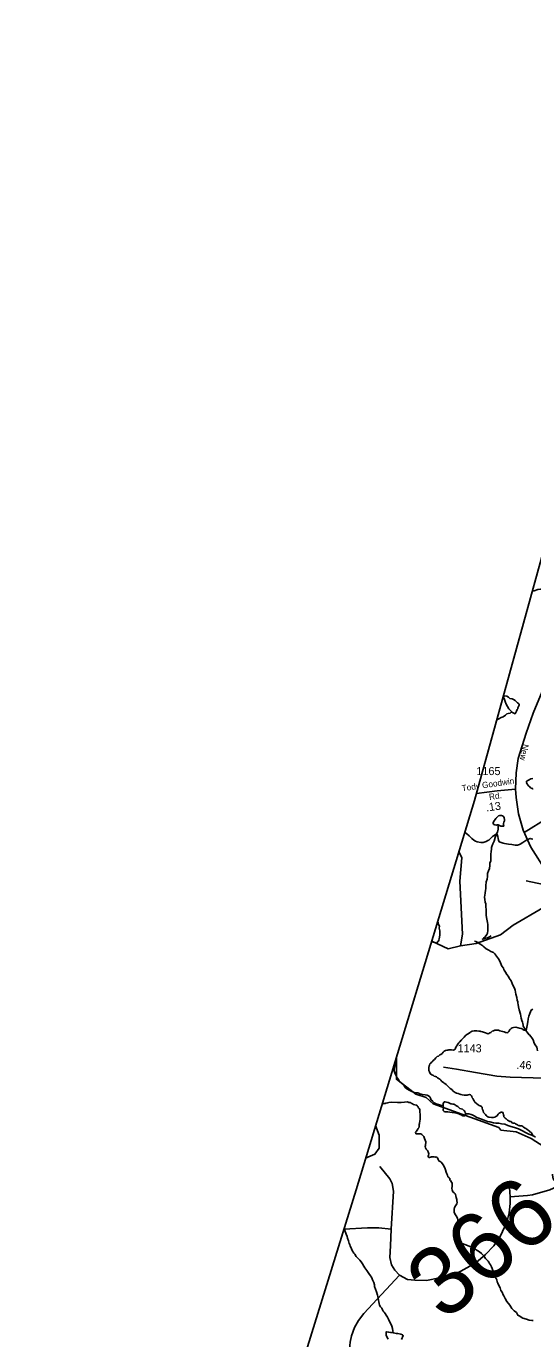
# Model space of a CAD drawing. Extents: x 2001466 to 2224147, y 644118 to 847247.
# Drawn here: x 2006818 to 2014651, y 709402 to 729712 of the extents above; entities that cross this region are included whole.
import ezdxf

# ---------------------------------------------------------------- set-up
doc = ezdxf.new("R2010")
doc.units = 0
for name, color, linetype in [('Exist Boundary Political CountyLine', 7, 'Continuous'), ('Exist Hydrographic Creek Single Shore', 7, 'Continuous'), ('Exist Hydrographic Misc Water Feature', 7, 'Continuous'), ('Exist Road Non-System Type 51', 7, 'Continuous'), ('Exist Road Secondary Mileage Hundredths English Label', 7, 'Continuous'), ('Exist Road Secondary Structure Standard Bridge CELL', 7, 'Continuous'), ('Exist Road Secondary Structure Standard Bridge Number Label', 7, 'Continuous'), ('Exist Road Secondary Type 20 Attributed', 7, 'Continuous'), ('Exist Road Secondary Type 41 Attributed', 7, 'Continuous'), ('Exist Road Secondary Type 51 Attributed', 7, 'Continuous'), ('Exist Road Secondary Type 51 Label', 7, 'Continuous'), ('Exist Road Secondary Type 51 Number Label', 7, 'Continuous')]:
    doc.layers.add(name, color=color, linetype=linetype)

msp = doc.modelspace()

# ---------------------------------------------------------------- linework, layer by layer
at = {"layer": 'Exist Boundary Political CountyLine'}
msp.add_lwpolyline([(2006818, 695750), (2007499, 697711), (2010413, 706845), (2011918, 711706), (2013749, 717730), (2014942, 722041), (2015285, 723239), (2015750, 724659), (2016153, 726118), (2016502, 727374), (2016861, 728619), (2017412, 730567), (2017757, 731851), (2018084, 732957), (2018350, 733870), (2018833, 735585), (2018918, 735898), (2019734, 740138), (2020503, 744108), (2021806, 746808), (2022822, 749625), (2023527, 751603)], dxfattribs=at)
at = {"layer": 'Exist Hydrographic Creek Single Shore'}
for points in [[(2013533, 715484), (2013775, 715519), (2014150, 715652), (2014349, 715802), (2014807, 716069), (2014941, 716176), (2014982, 716203), (2015055, 716229), (2015100, 716249), (2015170, 716309), (2015479, 716531)], [(2013088, 715555), (2013341, 715436), (2013533, 715484)]]:
    msp.add_lwpolyline(points, dxfattribs=at)
at = {"layer": 'Exist Hydrographic Misc Water Feature'}
for points in [[(2014986, 721093), (2014988, 721081), (2014988, 721063), (2014986, 721041), (2014980, 721031), (2014966, 721015), (2014938, 721007), (2014898, 721013), (2014866, 721017), (2014812, 721011), (2014772, 721001), (2014730, 720995), (2014672, 720977), (2014646, 720974)], [(2014331, 719099), (2014281, 719151), (2014239, 719219), (2014225, 719261), (2014215, 719293), (2014203, 719319), (2014201, 719331), (2014211, 719353), (2014249, 719343), (2014275, 719329), (2014283, 719323), (2014299, 719311), (2014331, 719305), (2014355, 719295), (2014379, 719279), (2014395, 719265), (2014417, 719243), (2014431, 719233), (2014437, 719227), (2014439, 719217), (2014439, 719207), (2014431, 719187), (2014423, 719165), (2014419, 719151), (2014411, 719137), (2014399, 719115), (2014389, 719091), (2014385, 719081), (2014379, 719073), (2014337, 719091), (2014331, 719099)], [(2014331, 719099), (2014313, 719091), (2014303, 719083), (2014271, 719075), (2014253, 719071), (2014229, 719053), (2014193, 719027), (2014165, 719015), (2014129, 718993), (2014094, 718977)], [(2014656, 717915), (2014646, 717911), (2014641, 717915), (2014619, 717927), (2014608, 717941), (2014593, 717953), (2014585, 717959), (2014574, 717973), (2014566, 717983), (2014553, 718007), (2014551, 718017), (2014566, 718035), (2014585, 718047), (2014621, 718065), (2014651, 718069)], [(2014114, 717353), (2014100, 717353), (2014090, 717351), (2014064, 717353), (2014050, 717361), (2014040, 717373), (2014040, 717383), (2014044, 717399), (2014056, 717415), (2014068, 717437), (2014080, 717451), (2014084, 717457), (2014090, 717465), (2014094, 717467), (2014106, 717479), (2014124, 717491), (2014142, 717499), (2014168, 717497), (2014184, 717495), (2014194, 717489), (2014204, 717479), (2014210, 717461), (2014214, 717439), (2014214, 717415), (2014204, 717395), (2014200, 717377), (2014200, 717359), (2014202, 717335), (2014188, 717333), (2014156, 717333), (2014128, 717349), (2014114, 717353)], [(2014088, 717211), (2014078, 717203), (2014070, 717201), (2014046, 717183), (2014028, 717173), (2014008, 717151), (2013972, 717119), (2013958, 717111), (2013930, 717095), (2013914, 717091), (2013882, 717083), (2013864, 717083), (2013846, 717083), (2013792, 717091), (2013766, 717101), (2013742, 717117), (2013710, 717145), (2013684, 717167), (2013670, 717183), (2013634, 717215), (2013608, 717237), (2013600, 717241)], [(2014088, 717211), (2014086, 717199), (2014068, 717159), (2014052, 717099), (2014044, 717081), (2014032, 717059), (2014016, 717021), (2014014, 717003), (2014014, 716977), (2014008, 716939), (2014004, 716899), (2014004, 716843), (2014002, 716799), (2013990, 716759), (2013986, 716727), (2013980, 716677), (2013968, 716641), (2013950, 716601), (2013950, 716557), (2013944, 716515), (2013931, 716471), (2013926, 716409), (2013928, 716381), (2013924, 716365), (2013920, 716345), (2013915, 716295), (2013907, 716237), (2013909, 716201), (2013917, 716159), (2013925, 716133), (2013927, 716093), (2013929, 716039), (2013931, 715951), (2013941, 715895), (2013949, 715845), (2013955, 715813), (2013957, 715785), (2013955, 715747), (2013955, 715721), (2013951, 715679), (2013939, 715659), (2013913, 715623), (2013887, 715599), (2013867, 715581)], [(2014114, 717353), (2014114, 717345), (2014118, 717287), (2014104, 717243), (2014088, 717211)], [(2014652, 717131), (2014626, 717139), (2014610, 717145), (2014562, 717123), (2014528, 717101), (2014514, 717089), (2014496, 717079), (2014458, 717057), (2014446, 717051), (2014432, 717045), (2014414, 717039), (2014380, 717041), (2014352, 717045), (2014326, 717051), (2014276, 717055), (2014216, 717065), (2014192, 717073), (2014162, 717083), (2014146, 717087), (2014134, 717093), (2014124, 717115), (2014114, 717145), (2014110, 717173), (2014104, 717191), (2014100, 717205), (2014088, 717211)], [(2013533, 715484), (2013566, 715661), (2013524, 716485), (2013557, 716845), (2013509, 716941)], [(2013181, 715862), (2013195, 715812), (2013207, 715788), (2013205, 715754), (2013215, 715714), (2013215, 715682), (2013213, 715654), (2013209, 715616), (2013203, 715591), (2013199, 715572), (2013193, 715556), (2013185, 715548), (2013175, 715532), (2013169, 715528), (2013159, 715522)], [(2013159, 715522), (2013149, 715526), (2013117, 715538), (2013097, 715548), (2013087, 715553)], [(2014544, 714173), (2014524, 714207), (2014504, 714241), (2014502, 714255), (2014500, 714279), (2014492, 714299), (2014484, 714327), (2014473, 714365), (2014460, 714423), (2014439, 714491), (2014431, 714537), (2014427, 714573), (2014423, 714593), (2014419, 714613), (2014411, 714639), (2014403, 714681), (2014391, 714733), (2014377, 714795), (2014367, 714829), (2014349, 714861), (2014335, 714897), (2014319, 714939), (2014289, 714981), (2014277, 715009), (2014251, 715037), (2014229, 715075), (2014211, 715103), (2014205, 715117), (2014199, 715135), (2014175, 715165), (2014155, 715217), (2014141, 715247), (2014121, 715283), (2014093, 715321), (2014087, 715329), (2014081, 715335), (2014065, 715357), (2014045, 715377), (2014003, 715395), (2013971, 715417), (2013933, 715435), (2013895, 715465), (2013877, 715481), (2013849, 715501), (2013825, 715517), (2013801, 715533), (2013769, 715547), (2013749, 715555)], [(2014007, 715637), (2013981, 715619), (2013953, 715607), (2013927, 715601), (2013895, 715589), (2013867, 715581)], [(2014544, 714173), (2014554, 714191), (2014562, 714223), (2014566, 714251), (2014569, 714273), (2014576, 714309), (2014580, 714341), (2014580, 714351), (2014590, 714391), (2014604, 714435), (2014615, 714461), (2014627, 714487), (2014655, 714503)], [(2014544, 714173), (2014520, 714177), (2014496, 714189), (2014488, 714195), (2014472, 714201), (2014446, 714207), (2014424, 714213), (2014390, 714221), (2014356, 714217), (2014334, 714213), (2014316, 714201), (2014300, 714187), (2014294, 714183), (2014290, 714177), (2014280, 714157), (2014268, 714143), (2014252, 714137), (2014236, 714139), (2014230, 714143), (2014208, 714149), (2014184, 714157), (2014162, 714163), (2014142, 714169), (2014122, 714175), (2014094, 714177), (2014078, 714177), (2014066, 714175), (2014042, 714169), (2014026, 714163), (2014016, 714155), (2014004, 714143), (2013990, 714133), (2013972, 714123), (2013956, 714119), (2013944, 714123), (2013918, 714135), (2013904, 714139), (2013890, 714147), (2013874, 714149), (2013850, 714157), (2013836, 714161), (2013816, 714163), (2013788, 714167), (2013766, 714169), (2013744, 714165), (2013714, 714159), (2013694, 714151), (2013682, 714143), (2013674, 714137), (2013666, 714131), (2013644, 714115), (2013616, 714097), (2013590, 714071), (2013578, 714057), (2013564, 714041), (2013550, 714027), (2013544, 714019), (2013536, 714011), (2013532, 714009), (2013524, 714003), (2013516, 713991), (2013506, 713979), (2013486, 713953), (2013476, 713935), (2013464, 713913), (2013458, 713899), (2013452, 713883), (2013440, 713875), (2013436, 713873), (2013418, 713869), (2013394, 713873), (2013368, 713875), (2013352, 713873), (2013340, 713869), (2013320, 713867), (2013300, 713863), (2013282, 713851), (2013266, 713837), (2013250, 713815), (2013232, 713801), (2013216, 713793), (2013192, 713777), (2013174, 713767), (2013154, 713751), (2013132, 713725), (2013112, 713709), (2013094, 713689), (2013084, 713681), (2013074, 713667), (2013062, 713655), (2013056, 713637), (2013048, 713625), (2013044, 713597), (2013042, 713575), (2013044, 713555), (2013050, 713543), (2013056, 713531), (2013062, 713519), (2013072, 713499), (2013090, 713487)], [(2014724, 713858), (2014722, 713888), (2014712, 713916), (2014690, 713948), (2014672, 713976), (2014658, 714025), (2014638, 714057), (2014620, 714078), (2014600, 714104), (2014596, 714107), (2014558, 714149), (2014544, 714173)], [(2014160, 712627), (2014126, 712670), (2013109, 713035), (2013001, 713136), (2012843, 713185), (2012543, 713418), (2012542, 713759)], [(2013079, 713094), (2013074, 713111), (2013068, 713125), (2013062, 713143), (2013040, 713159), (2013018, 713169), (2012986, 713177), (2012946, 713181), (2012928, 713187), (2012916, 713189), (2012896, 713199), (2012890, 713201), (2012874, 713207), (2012850, 713207), (2012816, 713214), (2012770, 713234), (2012748, 713244), (2012704, 713268), (2012680, 713292), (2012664, 713316), (2012628, 713350), (2012590, 713384), (2012576, 713412), (2012556, 713440), (2012534, 713478), (2012520, 713516), (2012508, 713550), (2012506, 713574), (2012514, 713596), (2012518, 713624), (2012522, 713654), (2012516, 713671), (2012518, 713678)], [(2013090, 713487), (2013114, 713473), (2013128, 713467), (2013148, 713461), (2013162, 713457), (2013180, 713441), (2013214, 713417), (2013230, 713405), (2013246, 713385), (2013272, 713365), (2013282, 713357), (2013294, 713349), (2013310, 713337), (2013334, 713313), (2013360, 713291), (2013374, 713273), (2013398, 713257), (2013422, 713235), (2013436, 713223), (2013450, 713213), (2013474, 713203), (2013496, 713197), (2013524, 713189), (2013540, 713183), (2013562, 713177), (2013592, 713173), (2013624, 713171), (2013638, 713173), (2013652, 713175), (2013674, 713179), (2013688, 713175), (2013694, 713171), (2013706, 713159), (2013708, 713151), (2013716, 713131), (2013722, 713117), (2013734, 713099), (2013746, 713083), (2013756, 713063), (2013774, 713049), (2013782, 713043), (2013788, 713037), (2013806, 713023), (2013822, 713013), (2013836, 713007), (2013850, 713001), (2013860, 712995), (2013868, 712985), (2013870, 712971), (2013876, 712947), (2013884, 712927), (2013892, 712905), (2013904, 712889), (2013920, 712873), (2013933, 712855), (2013941, 712847), (2013958, 712835), (2013971, 712831), (2014015, 712825), (2014042, 712825), (2014063, 712831), (2014080, 712841), (2014100, 712853), (2014108, 712861), (2014116, 712875), (2014126, 712887), (2014132, 712893), (2014152, 712905), (2014164, 712907), (2014170, 712907), (2014182, 712907), (2014192, 712893), (2014200, 712869), (2014204, 712851), (2014206, 712837), (2014224, 712813), (2014242, 712803), (2014252, 712795), (2014262, 712785), (2014270, 712779), (2014299, 712765), (2014316, 712761), (2014331, 712745), (2014347, 712738), (2014356, 712738), (2014369, 712736), (2014374, 712736), (2014387, 712726), (2014403, 712718), (2014414, 712712), (2014427, 712704), (2014443, 712700), (2014454, 712698), (2014467, 712698), (2014483, 712698), (2014499, 712688), (2014510, 712678), (2014534, 712662), (2014546, 712654), (2014558, 712644)], [(2012323, 713036), (2012330, 713038), (2012346, 713042), (2012368, 713042), (2012381, 713048), (2012407, 713052), (2012423, 713056), (2012468, 713064), (2012559, 713060), (2012617, 713060), (2012670, 713062), (2012716, 713066), (2012737, 713060), (2012763, 713056), (2012773, 713048), (2012792, 713035), (2012808, 713025), (2012830, 713021), (2012848, 713017), (2012856, 713015), (2012864, 713007), (2012869, 713001), (2012872, 712997), (2012885, 712977), (2012893, 712965), (2012903, 712947), (2012906, 712915), (2012909, 712871), (2012911, 712849), (2012911, 712821), (2012909, 712795), (2012903, 712773), (2012901, 712733), (2012897, 712717), (2012893, 712685), (2012887, 712665), (2012881, 712657), (2012873, 712647), (2012863, 712629), (2012853, 712615), (2012841, 712605), (2012837, 712595), (2012841, 712581), (2012845, 712575), (2012853, 712573), (2012865, 712573), (2012881, 712573), (2012899, 712573), (2012911, 712575), (2012921, 712573), (2012937, 712561), (2012953, 712549), (2012967, 712529), (2012979, 712501), (2012985, 712475), (2012997, 712447), (2012999, 712435), (2012995, 712407), (2012995, 712393), (2012989, 712375), (2012991, 712357), (2013001, 712337), (2013021, 712317), (2013031, 712303), (2013035, 712293), (2013041, 712279), (2013043, 712261), (2013037, 712243), (2013033, 712229), (2013035, 712215), (2013043, 712209), (2013049, 712205), (2013059, 712207), (2013067, 712209), (2013077, 712211), (2013087, 712215), (2013123, 712219), (2013145, 712213), (2013159, 712215), (2013173, 712205), (2013183, 712193), (2013187, 712177), (2013195, 712163), (2013201, 712153), (2013219, 712145), (2013237, 712133), (2013257, 712107), (2013267, 712095), (2013273, 712087), (2013277, 712073), (2013291, 712049), (2013303, 712015), (2013313, 711981), (2013321, 711955), (2013331, 711931), (2013339, 711909), (2013351, 711895), (2013359, 711887), (2013369, 711885)], [(2013268, 713015), (2013258, 713013), (2013226, 713017), (2013192, 713027), (2013172, 713033), (2013146, 713041), (2013126, 713051), (2013110, 713069), (2013102, 713079), (2013090, 713091), (2013079, 713094)], [(2013268, 713015), (2013268, 713025), (2013266, 713035), (2013268, 713043), (2013274, 713055), (2013278, 713061), (2013286, 713067), (2013298, 713067), (2013316, 713063), (2013342, 713055), (2013382, 713039), (2013394, 713035), (2013414, 713033), (2013430, 713031), (2013440, 713029), (2013450, 713021), (2013464, 713013), (2013490, 712995), (2013504, 712983), (2013518, 712971), (2013526, 712967), (2013544, 712961), (2013566, 712953), (2013584, 712935), (2013594, 712927), (2013599, 712919), (2013607, 712899), (2013609, 712891)], [(2013609, 712891), (2013613, 712890), (2013610, 712867), (2013604, 712857), (2013594, 712851), (2013572, 712851), (2013560, 712855), (2013544, 712865), (2013527, 712871), (2013517, 712877), (2013495, 712887), (2013472, 712893), (2013447, 712899), (2013405, 712903), (2013371, 712907), (2013336, 712913), (2013296, 712915), (2013283, 712919), (2013275, 712925), (2013268, 712933), (2013267, 712937), (2013268, 712955), (2013270, 712975), (2013270, 712987), (2013268, 712997), (2013268, 713015)], [(2012221, 712701), (2012277, 712553), (2012277, 712353), (2012210, 712260), (2012067, 712194)], [(2014647, 712548), (2014639, 712550), (2014590, 712566), (2014538, 712592), (2014491, 712620), (2014430, 712648), (2014369, 712671), (2014313, 712687), (2014268, 712701), (2014218, 712723), (2014170, 712725), (2014128, 712737), (2014079, 712737), (2014045, 712741), (2013989, 712757), (2013949, 712763), (2013899, 712783), (2013859, 712801), (2013801, 712821), (2013787, 712825), (2013745, 712849), (2013713, 712867), (2013698, 712873), (2013665, 712883), (2013634, 712883), (2013618, 712889), (2013613, 712890), (2013609, 712891)], [(2014626, 712502), (2014393, 712602), (2014160, 712627)], [(2014558, 712644), (2014566, 712638), (2014578, 712630), (2014594, 712618), (2014608, 712606), (2014623, 712596), (2014632, 712586), (2014639, 712578), (2014640, 712572), (2014645, 712568), (2014648, 712558), (2014647, 712548)], [(2016319, 710279), (2015952, 710405), (2015802, 710562), (2015485, 710720), (2015352, 710831), (2015244, 711013), (2015210, 711204), (2015169, 711271), (2015127, 711672), (2014968, 711878), (2014901, 712270), (2014826, 712370), (2014626, 712502)], [(2014696, 712524), (2014688, 712528), (2014647, 712548)], [(2013405, 711789), (2013403, 711807), (2013397, 711823), (2013379, 711851), (2013369, 711857), (2013369, 711867), (2013369, 711885)], [(2014656, 709684), (2014638, 709682), (2014596, 709690), (2014556, 709706), (2014496, 709722), (2014440, 709754), (2014422, 709766), (2014398, 709806), (2014362, 709836), (2014328, 709872), (2014296, 709920), (2014252, 709980), (2014226, 710022), (2014214, 710046), (2014202, 710064), (2014194, 710082), (2014176, 710120), (2014158, 710148), (2014146, 710192), (2014128, 710226), (2014110, 710260), (2014100, 710284), (2014094, 710312), (2014086, 710334), (2014072, 710354), (2014064, 710374), (2014056, 710408), (2014038, 710446), (2014024, 710488), (2014014, 710516), (2013996, 710546), (2013984, 710567), (2013974, 710585), (2013962, 710601), (2013946, 710619), (2013922, 710645), (2013894, 710683), (2013858, 710723), (2013828, 710749), (2013778, 710777), (2013768, 710787), (2013746, 710801), (2013708, 710821), (2013676, 710831), (2013614, 710857), (2013562, 710875), (2013539, 710885), (2013515, 710899), (2013488, 710919), (2013480, 710933), (2013470, 710941), (2013470, 710959), (2013470, 710971), (2013470, 710985), (2013466, 710995), (2013462, 711009), (2013468, 711039), (2013477, 711073), (2013476, 711113), (2013476, 711145), (2013473, 711167), (2013479, 711189), (2013492, 711213), (2013492, 711237), (2013487, 711269), (2013465, 711305), (2013455, 711319), (2013437, 711355), (2013437, 711377), (2013435, 711405), (2013439, 711435), (2013455, 711459), (2013465, 711473), (2013477, 711489), (2013481, 711509), (2013479, 711535), (2013475, 711547), (2013475, 711555), (2013471, 711573), (2013469, 711585), (2013461, 711613), (2013457, 711635), (2013449, 711645), (2013437, 711659), (2013415, 711677), (2013405, 711705), (2013401, 711725), (2013405, 711761), (2013405, 711789)], [(2012492, 709493), (2012487, 709525), (2012482, 709559), (2012472, 709595), (2012454, 709635), (2012437, 709669), (2012420, 709707), (2012406, 709737), (2012386, 709769), (2012368, 709791), (2012352, 709813), (2012338, 709831), (2012328, 709849), (2012316, 709873), (2012294, 709895), (2012282, 709921), (2012276, 709947), (2012270, 709973), (2012268, 709991), (2012260, 710029), (2012256, 710055), (2012252, 710076), (2012236, 710126), (2012218, 710171), (2012206, 710208), (2012202, 710238), (2012192, 710270), (2012174, 710312), (2012160, 710342), (2012154, 710362), (2012146, 710372), (2012128, 710398), (2012106, 710426), (2012084, 710460), (2012054, 710498), (2012040, 710526), (2012018, 710562), (2011998, 710590), (2011976, 710616), (2011954, 710638), (2011922, 710672), (2011898, 710708), (2011884, 710726), (2011860, 710766), (2011836, 710820), (2011828, 710834), (2011820, 710858), (2011812, 710876), (2011802, 710916), (2011788, 710958), (2011780, 710986), (2011764, 711022), (2011746, 711078), (2011735, 711115)], [(2012492, 709493), (2012466, 709499), (2012453, 709497), (2012425, 709501), (2012385, 709511), (2012383, 709497), (2012383, 709479), (2012386, 709457), (2012394, 709433), (2012413, 709397)], [(2012622, 709391), (2012649, 709451), (2012638, 709463), (2012609, 709473), (2012564, 709481), (2012540, 709485), (2012497, 709493), (2012492, 709493)]]:
    msp.add_lwpolyline(points, dxfattribs=at)
at = {"layer": 'Exist Road Non-System Type 51'}
for points in [[(2014519, 717236), (2014885, 717463), (2015336, 716757)], [(2014303, 711597), (2014568, 711616), (2014645, 711629), (2014914, 711706), (2015179, 711827), (2015419, 711978), (2015608, 712125), (2016167, 712627), (2016202, 712661), (2016254, 712704), (2016299, 712750)], [(2012462, 711098), (2012499, 711684), (2012476, 711804), (2012439, 711878), (2012288, 712069)], [(2014303, 711597), (2014284, 711815)], [(2012590, 710385), (2012714, 710319), (2012825, 710306), (2013009, 710305), (2013408, 710388), (2013539, 710446), (2013773, 710574), (2013923, 710705), (2014047, 710842), (2014153, 710996), (2014252, 711207), (2014284, 711348), (2014303, 711495), (2014303, 711597)], [(2012462, 711098), (2012272, 711118), (2012094, 711118), (2011729, 711095)], [(2012590, 710385), (2012516, 710462), (2012469, 710546), (2012442, 710660), (2012449, 710840), (2012462, 711098)], [(2011807, 709140), (2011825, 709349), (2011850, 709448), (2011894, 709578), (2011954, 709682), (2012041, 709793), (2012590, 710385)]]:
    msp.add_lwpolyline(points, dxfattribs=at)
at = {"layer": 'Exist Road Secondary Structure Standard Bridge CELL'}
msp.add_line((2014548, 716488), (2014818, 716430), dxfattribs=at)
at = {"layer": 'Exist Road Secondary Type 20 Attributed'}
msp.add_lwpolyline([(2015674, 713399), (2015401, 713412), (2014833, 713435), (2014303, 713451), (2014096, 713463), (2013767, 713521), (2013470, 713575), (2013269, 713604)], dxfattribs=at)
at = {"layer": 'Exist Road Secondary Type 41 Attributed'}
msp.add_lwpolyline([(2014384, 717906), (2014100, 717881), (2013779, 717838)], dxfattribs=at)
at = {"layer": 'Exist Road Secondary Type 51 Attributed'}
for points in [[(2014384, 717906), (2014396, 718159), (2014428, 718381), (2014552, 718772), (2014656, 719081), (2014821, 719477), (2014902, 719648), (2015001, 719816), (2015216, 720181), (2015372, 720421), (2015485, 720589), (2015523, 720673), (2015553, 720785), (2015589, 721048), (2015595, 721118), (2015623, 721186)], [(2015100, 716249), (2014865, 716628), (2014623, 717009), (2014503, 717271), (2014432, 717522), (2014394, 717779), (2014384, 717906)]]:
    msp.add_lwpolyline(points, dxfattribs=at)

# ---------------------------------------------------------------- texts
at = {"layer": 'Exist Road Secondary Mileage Hundredths English Label'}
for s, rotation, p in [('.13', 7.5446, (2013935, 717560)), ('.46', 358.2735, (2014398, 713578))]:
    msp.add_text(s, height=125, rotation=rotation, dxfattribs=at).set_placement(p)
at = {"layer": 'Exist Road Secondary Structure Standard Bridge Number Label'}
msp.add_text('366', height=1066.3, rotation=40, dxfattribs=at).set_placement((2013282, 709652))
at = {"layer": 'Exist Road Secondary Type 51 Label'}
for s, rotation, p in [('New', 259.211, (2014498, 718610)), ('Tody Goodwin', 8.3584, (2013560, 717872)), ('Rd.', 8.3584, (2013982, 717738))]:
    msp.add_text(s, height=95, rotation=rotation, dxfattribs=at).set_placement(p)
at = {"layer": 'Exist Road Secondary Type 51 Number Label'}
for s, p in [('1165', (2013780, 718124)), ('1143', (2013489, 713834))]:
    msp.add_text(s, height=125, dxfattribs=at).set_placement(p)

doc.saveas('drawing.dxf')
